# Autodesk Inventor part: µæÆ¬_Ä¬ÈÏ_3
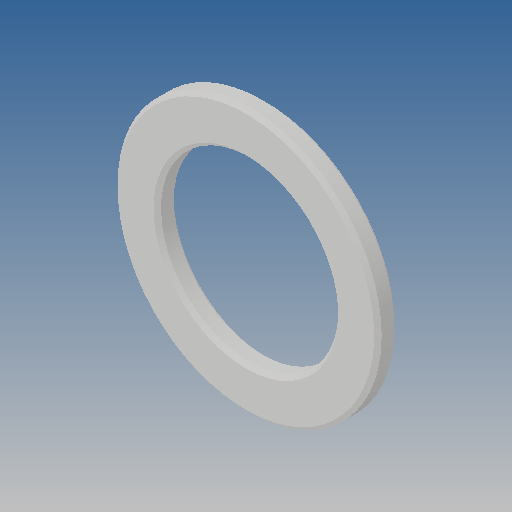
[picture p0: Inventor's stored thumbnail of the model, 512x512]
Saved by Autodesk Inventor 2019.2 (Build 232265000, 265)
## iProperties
Created: 2013-03
Part Number: µæÆ¬_Ä¬ÈÏ_3
Material: Ogólny
Document SubType Name: Modeling
Designer: CADENGINEERING4
Density: 1 g/cm^3
Appearance: Domyślna
Author: CADENGINEERING4
Revision Number: ÈÎºÎ
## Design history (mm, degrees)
feature "NONE"
node "Bryła1"
